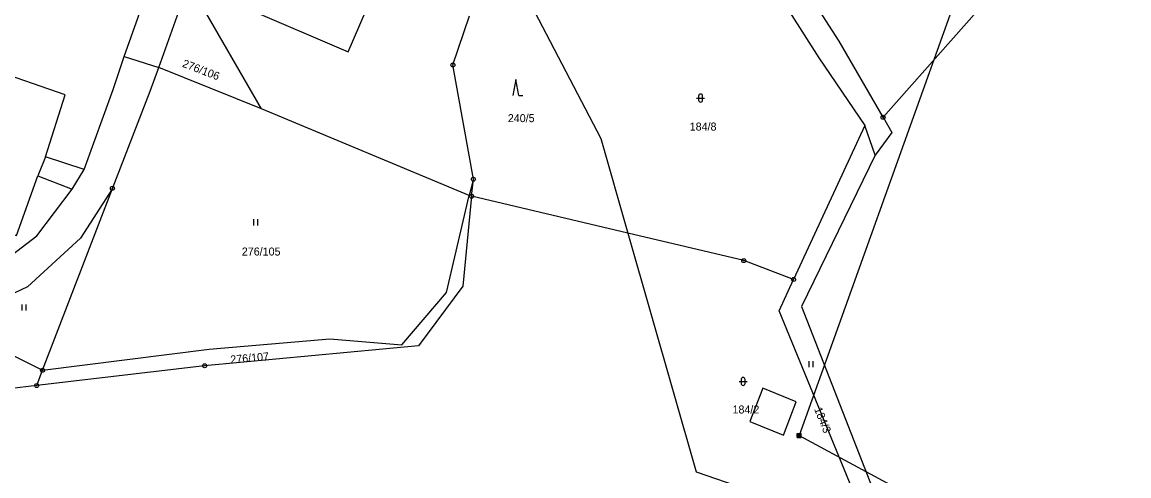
# Model space of a CAD drawing. Extents: x -745926 to -742978, y -968282 to -965689.
# Drawn here: x -744649.7 to -744511.4, y -967145.7 to -967089.1 of the extents above; entities that cross this region are included whole.
import ezdxf

# ---------------------------------------------------------------- set-up
doc = ezdxf.new("R2010")
doc.units = 0
for name, color, linetype in [('Hranice parcel', 7, 'Continuous'), ('Parcelní čísla', 7, 'Continuous'), ('Poz předměty', 7, 'Continuous'), ('Vnitřní kresba', 7, 'Continuous'), ('Věcná břemena k části', 7, 'Continuous'), ('Značky bodu BP', 7, 'Continuous'), ('Značky kultur', 7, 'Continuous')]:
    doc.layers.add(name, color=color, linetype=linetype)

msp = doc.modelspace()

# ---------------------------------------------------------------- linework, layer by layer
at = {"layer": 'Hranice parcel'}
for p, q in [((-744637.01, -967093.36), (-744633.34, -967083.14)), ((-744632.68, -967094.73), (-744628.92, -967084.21)), ((-744619.82, -967099.9), (-744628.92, -967084.21)), ((-744637.01, -967093.36), (-744632.68, -967094.73)), ((-744619.82, -967099.9), (-744632.68, -967094.73)), ((-744593.89, -967110.73), (-744619.82, -967099.9)), ((-744542.16, -967100.96), (-744541.05, -967102.88)), ((-744643.49, -967109.92), (-744642.01, -967107.49)), ((-744647.2, -967132.55), (-744638.47, -967109.84)), ((-744593.36, -967108.69), (-744593.89, -967110.73)), ((-744593.57, -967110.81), (-744593.36, -967108.69)), ((-744574.04, -967115.43), (-744593.57, -967110.81)), ((-744574.04, -967115.43), (-744565.51, -967145.23)), ((-744555.14, -967125.12), (-744553.33, -967121.21)), ((-744542.61, -967155.54), (-744555.14, -967125.12)), ((-744652.27, -967129.98), (-744647.2, -967132.55)), ((-744647.93, -967134.45), (-744647.2, -967132.55))]:
    msp.add_line(p, q, dxfattribs=at)
for points in [[(-744691.08, -967009.49), (-744698.98, -967032.76), (-744695.35, -967034.03), (-744697.16, -967038.95), (-744703.88, -967036.64), (-744713.79, -967065.36), (-744706.42, -967068.2), (-744712.77, -967086.04), (-744703.58, -967089), (-744701.81, -967089.59), (-744695.24, -967091.66), (-744693.5, -967092.27), (-744696.04, -967099.62), (-744650.43, -967115.72), (-744647.79, -967108.29), (-744643.49, -967109.92)], [(-744702.72, -967010.81), (-744704.58, -967014.37), (-744720.18, -967059.59), (-744722.02, -967065.75), (-744721.47, -967072.64), (-744717.1, -967081.95), (-744707.96, -967096.22), (-744700.48, -967104.95), (-744692.45, -967111.29), (-744683.59, -967116.31), (-744671.48, -967120.93), (-744660.56, -967122.15), (-744652.94, -967119.57), (-744647.9, -967115.77), (-744643.49, -967109.92)], [(-744567.27, -967053.53), (-744543.15, -967053.11), (-744531.29, -967056.12), (-744517.27, -967060.7), (-744511.44, -967066.31), (-744511.55, -967066.43), (-744542.16, -967100.96)], [(-744642.01, -967107.49), (-744646.82, -967105.88), (-744644.38, -967098.17), (-744690.01, -967082.29), (-744692.56, -967089.69), (-744694.24, -967089.14), (-744700.9, -967086.97), (-744702.61, -967086.38), (-744709.09, -967084.14), (-744703.71, -967069.13), (-744697.29, -967071), (-744692.99, -967058.57), (-744683.72, -967063.97), (-744686.55, -967072.36), (-744669.16, -967078.42), (-744664.11, -967064.32), (-744654.06, -967067.83), (-744655.83, -967072.99), (-744639.35, -967078.71), (-744637.23, -967079.09), (-744633.34, -967083.14)], [(-744542.16, -967100.96), (-744547.65, -967091.47), (-744553.41, -967082.53), (-744560.46, -967077.14), (-744573.49, -967072.97), (-744578.21, -967072.89), (-744588.21, -967077.31)], [(-744575.69, -967075.49), (-744561.6, -967080.68), (-744555.69, -967084.89), (-744550.18, -967093.52), (-744544.43, -967101.97), (-744553.33, -967121.21)], [(-744618.11, -967080.52), (-744621.15, -967087.57), (-744609.02, -967092.81), (-744605.95, -967085.7)], [(-744589.6, -967080.29), (-744577.43, -967103.6), (-744574.04, -967115.43)], [(-744593.36, -967108.69), (-744595.92, -967094.43), (-744593.86, -967088.29)], [(-744647.93, -967134.45), (-744654.85, -967135.27), (-744688.93, -967128.97), (-744711.46, -967111.47), (-744730.96, -967089.88)], [(-744642.01, -967107.49), (-744638.39, -967097.49), (-744637.01, -967093.36)], [(-744638.47, -967109.84), (-744633.73, -967097.72), (-744632.68, -967094.73)], [(-744541.05, -967102.88), (-744543.16, -967105.71), (-744552.35, -967124.59), (-744540.04, -967156.14)], [(-744638.47, -967109.84), (-744642.47, -967116.04), (-744649.07, -967122.13), (-744655.46, -967125.12), (-744660.29, -967126.5)], [(-744593.57, -967110.81), (-744594.69, -967122.04), (-744600.21, -967129.48), (-744626.94, -967131.98), (-744647.93, -967134.45)], [(-744647.2, -967132.55), (-744626.39, -967129.91), (-744611.28, -967128.62), (-744602.29, -967129.37), (-744596.7, -967122.82), (-744593.89, -967110.73)], [(-744553.33, -967121.21), (-744559.57, -967118.86), (-744574.04, -967115.43)], [(-744565.51, -967145.23), (-744560.56, -967146.93), (-744558.67, -967147.58), (-744561.78, -967155.78), (-744563.9, -967157.06)]]:
    msp.add_lwpolyline(points, dxfattribs=at)
at = {"layer": 'Poz předměty'}
for p, q in [((-744514.35, -967033.93), (-744552.63, -967140.68)), ((-744552.88, -967140.43), (-744552.38, -967140.43)), ((-744552.88, -967140.93), (-744552.88, -967140.43)), ((-744552.88, -967140.53), (-744552.38, -967140.53)), ((-744552.88, -967140.63), (-744552.38, -967140.63)), ((-744552.88, -967140.73), (-744552.38, -967140.73)), ((-744552.88, -967140.83), (-744552.38, -967140.83)), ((-744552.88, -967140.93), (-744552.38, -967140.93)), ((-744552.78, -967140.93), (-744552.78, -967140.43)), ((-744552.68, -967140.93), (-744552.68, -967140.43)), ((-744552.63, -967140.68), (-744526.79, -967154.62)), ((-744552.58, -967140.93), (-744552.58, -967140.43)), ((-744552.48, -967140.93), (-744552.48, -967140.43)), ((-744552.38, -967140.93), (-744552.38, -967140.43))]:
    msp.add_line(p, q, dxfattribs=at)
at = {"layer": 'Vnitřní kresba'}
for p, q in [((-744543.16, -967105.71), (-744544.43, -967101.97)), ((-744646.82, -967105.88), (-744647.79, -967108.29))]:
    msp.add_line(p, q, dxfattribs=at)
at = {"layer": 'Věcná břemena k části'}
msp.add_lwpolyline([(-744557.2, -967134.79), (-744558.81, -967138.96), (-744554.62, -967140.65), (-744553.01, -967136.48)], close=True, dxfattribs=at)
at = {"layer": 'Značky bodu BP'}
for centre, radius in [((-744595.92, -967094.43), 0.25), ((-744595.92, -967094.43), 0.0152), ((-744542.16, -967100.96), 0.25), ((-744542.16, -967100.96), 0.0152), ((-744593.36, -967108.69), 0.25), ((-744638.47, -967109.84), 0.25), ((-744638.47, -967109.84), 0.0152), ((-744593.36, -967108.69), 0.0152), ((-744593.57, -967110.81), 0.25), ((-744593.57, -967110.81), 0.0152), ((-744559.57, -967118.86), 0.25), ((-744559.57, -967118.86), 0.0152), ((-744553.33, -967121.21), 0.25), ((-744553.33, -967121.21), 0.0152), ((-744626.94, -967131.98), 0.25), ((-744626.94, -967131.98), 0.0152), ((-744647.2, -967132.55), 0.25), ((-744647.2, -967132.55), 0.0152), ((-744647.93, -967134.45), 0.25), ((-744647.93, -967134.45), 0.0152)]:
    msp.add_circle(centre, radius, dxfattribs=at)
at = {"layer": 'Značky kultur'}
for p, q in [((-744588.03, -967096.23), (-744588.41, -967098.23)), ((-744587.66, -967098.23), (-744588.03, -967096.23)), ((-744587.66, -967098.23), (-744587.16, -967098.23)), ((-744565.46, -967098.56), (-744564.46, -967098.56)), ((-744565.21, -967098.31), (-744565.21, -967098.81)), ((-744564.71, -967098.81), (-744564.71, -967098.31)), ((-744620.78, -967114.45), (-744620.78, -967113.7)), ((-744620.28, -967114.45), (-744620.28, -967113.7)), ((-744649.75, -967125.08), (-744649.75, -967124.33)), ((-744649.24, -967125.08), (-744649.24, -967124.33)), ((-744551.38, -967132.17), (-744551.38, -967131.42)), ((-744550.88, -967132.17), (-744550.88, -967131.42)), ((-744560.15, -967133.94), (-744559.15, -967133.94)), ((-744559.9, -967133.69), (-744559.9, -967134.19)), ((-744559.4, -967134.19), (-744559.4, -967133.69))]:
    msp.add_line(p, q, dxfattribs=at)
for centre, start, end in [((-744564.96, -967098.31), 0, 180), ((-744564.96, -967098.81), 180, 359.9879), ((-744559.65, -967133.69), 0, 180), ((-744559.65, -967134.19), 180, 359.9879)]:
    msp.add_arc(centre, 0.25, start, end, dxfattribs=at)

# ---------------------------------------------------------------- texts
at = {"layer": 'Parcelní čísla'}
for s, rotation, p in [('276/106', 339, (-744629.82, -967094.63)), ('276/107', 5, (-744623.68, -967131.71)), ('184/3', 292, (-744550.79, -967137.39))]:
    msp.add_text(s, height=1, rotation=rotation, dxfattribs=at).set_placement(p)
for s, p in [('240/5', (-744589.05, -967101.57)), ('184/8', (-744566.32, -967102.62)), ('276/105', (-744622.29, -967118.22)), ('184/2', (-744560.97, -967137.94))]:
    msp.add_text(s, height=1, dxfattribs=at).set_placement(p)

doc.saveas('drawing.dxf')
